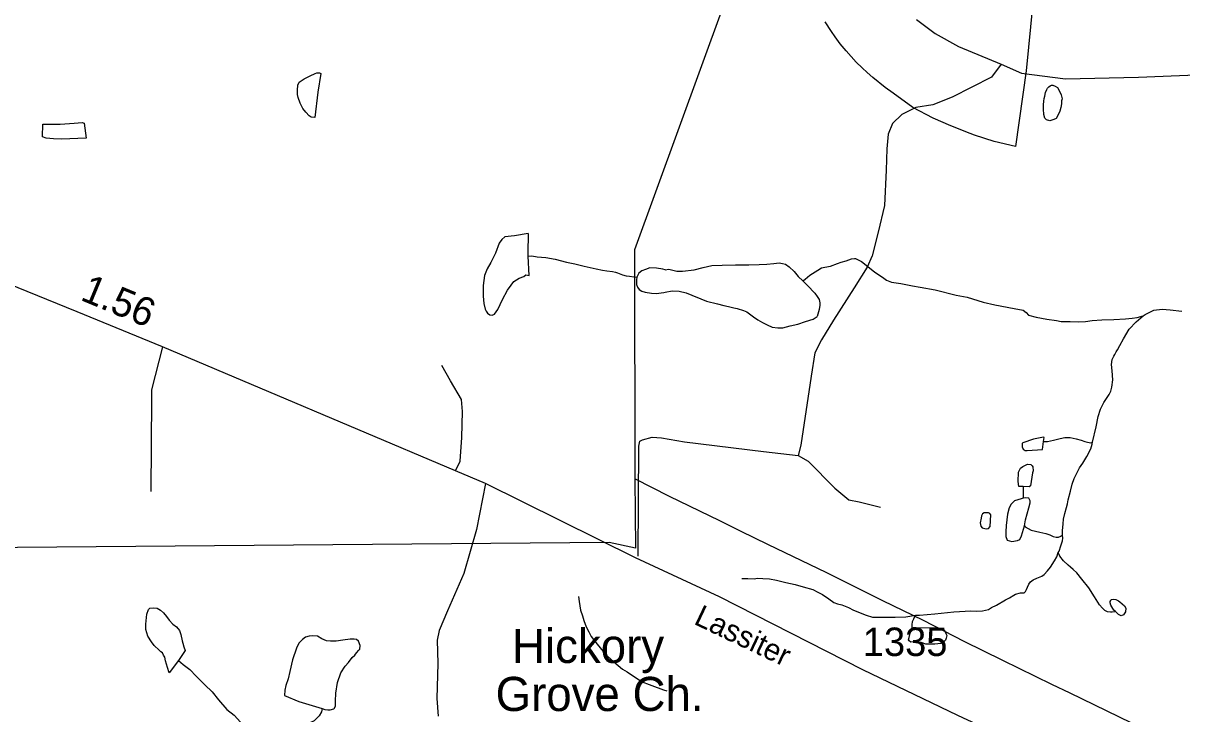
# Model space of a CAD drawing. Extents: x 2082433 to 2279600, y 546599 to 755198.
# Drawn here: x 2146074 to 2151168, y 635593 to 638629 of the extents above; entities that cross this region are included whole.
import ezdxf

# ---------------------------------------------------------------- set-up
doc = ezdxf.new("R2010")
doc.units = 0
for name, color, linetype in [('Exist Boundary Political Fire Districts', 7, 'Continuous'), ('Exist Cultural Church Label', 7, 'Continuous'), ('Exist Hydrographic Misc Water Feature', 7, 'Continuous'), ('Exist Road Non-System Type 51', 7, 'Continuous'), ('Exist Road Secondary Mileage Hundredths English Label', 7, 'Continuous'), ('Exist Road Secondary Type 51 Attributed', 7, 'Continuous'), ('Exist Road Secondary Type 51 Label', 7, 'Continuous'), ('Exist Road Secondary Type 51 Number Label', 7, 'Continuous')]:
    doc.layers.add(name, color=color, linetype=linetype)

msp = doc.modelspace()

# ---------------------------------------------------------------- linework, layer by layer
at = {"layer": 'Exist Boundary Political Fire Districts'}
for points in [[(2149345.1, 639234.6), (2148761.9, 637632), (2148762.7, 636625.8)], [(2150513, 638716), (2150482.9, 638419.1), (2150437, 638086.3), (2150343.1, 638109), (2150255.7, 638136.9), (2150236.4, 638143.4), (2150151.5, 638177.4), (2150074.9, 638211.1), (2149985, 638257.7), (2149898.1, 638320.6), (2149863.4, 638346.3), (2149809.9, 638389.3), (2149783.7, 638412.2), (2149761.9, 638431.9), (2149736.5, 638457), (2149713.3, 638481.9), (2149691.4, 638506.9), (2149665.2, 638538.5), (2149643.8, 638568), (2149627.4, 638591.5), (2149599.5, 638635.2)], [(2148762.7, 636625.8), (2148766, 636321.8), (2148650.1, 636346.6), (2144312.3, 636309), (2140471.4, 635994.8)], [(2152256, 634907.7), (2152199.6, 634933.1), (2152108.6, 634977), (2152016.1, 635021.2), (2151940.2, 635057.1), (2151321.2, 635370.7), (2150676.1, 635684), (2150596.7, 635722.7), (2150381.2, 635828.1), (2150211.2, 635910.6), (2150032.4, 636002.9), (2149852.8, 636090.6), (2149603.8, 636215), (2149351, 636336.1), (2149227.6, 636396.8), (2149135.9, 636441.9), (2148915.7, 636549.1), (2148762.7, 636625.8)]]:
    msp.add_lwpolyline(points, dxfattribs=at)
at = {"layer": 'Exist Hydrographic Misc Water Feature'}
msp.add_line((2150998.2, 637341.8), (2151006, 637347.9), dxfattribs=at)
for points in [[(2147369, 638325.8), (2147355.4, 638213.8), (2147339.7, 638215.8), (2147331.3, 638222), (2147315.7, 638237.7), (2147303.4, 638253.8), (2147291.7, 638277.5), (2147282.9, 638301.5), (2147279.4, 638315.4), (2147279.4, 638333.6), (2147280.8, 638355.7), (2147287, 638369.4), (2147308.9, 638383.5), (2147334.7, 638397.9), (2147356.7, 638407.9), (2147364.7, 638410), (2147376.6, 638409.8), (2147382.7, 638408.1), (2147369, 638325.8)], [(2150562.7, 638297.5), (2150564.7, 638307.7), (2150568.8, 638323.7), (2150574.8, 638337.4), (2150576.8, 638343.6), (2150582.8, 638349.6), (2150588.7, 638353.5), (2150594.5, 638355.9), (2150600.4, 638355.8), (2150610.9, 638351.8), (2150620.9, 638345.8), (2150630.5, 638329.8), (2150636.9, 638313.8), (2150641, 638296.1), (2150638.9, 638288), (2150639.2, 638274.1), (2150635.3, 638258.1), (2150631.2, 638242.1), (2150621.5, 638220), (2150615.4, 638210), (2150605.3, 638205.8), (2150587.7, 638199.6), (2150573.3, 638203.7), (2150565.3, 638211.5), (2150561.2, 638227.5), (2150559.2, 638251.3), (2150559.4, 638269.6), (2150560.6, 638285.6), (2150562.7, 638297.5)], [(2146242.6, 638119), (2146206.3, 638120.8), (2146174.3, 638122.8), (2146158.4, 638128.9), (2146160, 638184.6), (2146190.3, 638184.9), (2146236.1, 638184.8), (2146297.6, 638189.3), (2146333.7, 638191.5), (2146341.9, 638189.5), (2146350.5, 638123.3), (2146242.6, 638119)], [(2148294, 637604.3), (2148294, 637622.2), (2148295.4, 637700.2), (2148293.2, 637704.2), (2148233.7, 637693.7), (2148191.7, 637689.5), (2148177.9, 637677.8), (2148165.8, 637661.4), (2148150, 637617.6), (2148130.1, 637577.6), (2148113.9, 637549.6), (2148102.5, 637519.3), (2148096.5, 637475.6), (2148096.5, 637429.4), (2148098.8, 637397.4), (2148104.7, 637371.3), (2148109.2, 637363.3), (2148115.4, 637353.5), (2148125.4, 637347.6), (2148135.3, 637345.7), (2148145.3, 637349.8), (2148160.9, 637369.7), (2148181, 637413.7), (2148202.9, 637455.9), (2148218.5, 637477.8), (2148230.4, 637493.9), (2148254.6, 637508.1), (2148274.1, 637516.1), (2148284.1, 637522.3), (2148298.3, 637520.1), (2148294, 637604.3)], [(2148294, 637604.3), (2148310, 637606.3), (2148334, 637602.3), (2148372.1, 637598.6), (2148412.1, 637590.9), (2148461.9, 637578.9), (2148499.6, 637571.2), (2148539.6, 637561.5), (2148592.1, 637549.5), (2148620, 637543.6), (2148640.3, 637539.8), (2148664.1, 637537.8), (2148678.4, 637534), (2148686, 637532), (2148708.4, 637522.2), (2148724.2, 637518.2), (2148740, 637516.2), (2148758.4, 637514.2), (2148772.2, 637512.5)], [(2148895.8, 637545), (2148911.8, 637547), (2148947.9, 637539.1), (2148971.7, 637538.8), (2149023.8, 637545.1), (2149063.5, 637555.3), (2149101.5, 637563.3), (2149147.4, 637565.7), (2149205.2, 637566.3), (2149263.5, 637566.4), (2149309.4, 637568.8), (2149343.4, 637568.9), (2149373.4, 637572.9), (2149397.2, 637575.4), (2149411.3, 637573.2), (2149425.7, 637569.5), (2149441.4, 637557.3), (2149463.6, 637537.3), (2149481.6, 637515.5), (2149502.1, 637495.8)], [(2149502.1, 637495.8), (2149511.6, 637503.7), (2149531.5, 637521.8), (2149567.6, 637543.9), (2149583.3, 637554.1), (2149597.7, 637556.4), (2149623.5, 637560.7), (2149653.5, 637572.7), (2149669.5, 637578.8), (2149691.2, 637584.8), (2149715.2, 637593), (2149729.1, 637594.9), (2149733.2, 637595.1), (2149759.1, 637581.1), (2149779.4, 637565.4), (2149817.5, 637533.7), (2149851.5, 637511.9), (2149869.6, 637499.9), (2149891.7, 637490), (2149931.7, 637484.4), (2149983.6, 637474.5), (2150017.8, 637468.5), (2150083.9, 637456.9), (2150176.1, 637433.7), (2150223.7, 637424), (2150294.1, 637402.4), (2150345.3, 637390.6), (2150430.6, 637374.1), (2150470.6, 637366.8), (2150482.9, 637356.8), (2150494.2, 637345)], [(2148895.8, 637545), (2148885.8, 637546.9), (2148857.9, 637552.7), (2148828.1, 637552.8), (2148809.7, 637546.6), (2148793.9, 637540.5), (2148780.2, 637530.4), (2148772.2, 637512.5)], [(2148772.2, 637512.5), (2148770.1, 637500.3), (2148770.1, 637480.4), (2148774.6, 637468.4), (2148782.2, 637458.3), (2148794.1, 637450.4), (2148808.2, 637446.6), (2148836.1, 637442.8), (2148858.3, 637440.7), (2148878.4, 637443), (2148890.5, 637444.7), (2148896.4, 637447.1)], [(2149502.1, 637495.8), (2149521.8, 637475.8), (2149554.4, 637442.1), (2149563.9, 637428.1), (2149573.9, 637414.4), (2149576.4, 637400.2), (2149576.4, 637390.1), (2149572.5, 637370), (2149564.5, 637340)], [(2148896.4, 637447.1), (2148926.4, 637453.1), (2148958.1, 637450.7), (2148988.3, 637443), (2149012.7, 637433.2), (2149052.5, 637417.4), (2149078.5, 637407.4), (2149126.3, 637395.7), (2149154.8, 637387.7), (2149174.5, 637383.9), (2149198.7, 637378.3), (2149212.8, 637374.1), (2149240.9, 637366.2), (2149254.6, 637360.5), (2149285.2, 637338.8)], [(2151006, 637347.9), (2151045.2, 637367.1), (2151080.8, 637371.1), (2151116.1, 637369), (2151167.8, 637363.2)], [(2149285.2, 637338.8), (2149304.1, 637325.4), (2149324.6, 637312.6), (2149345.1, 637302.6), (2149366.6, 637292.4), (2149390.8, 637289.2), (2149413.4, 637289.8), (2149445.5, 637298.7), (2149479.4, 637306.2), (2149512.8, 637317.8), (2149547.3, 637328), (2149564.5, 637340)], [(2150494.2, 637345), (2150528, 637337), (2150573.9, 637327.3), (2150616, 637321.7), (2150637.9, 637318), (2150676.3, 637317.9), (2150714.2, 637316.2), (2150744.1, 637318.1), (2150773.9, 637322.6), (2150815.9, 637324.7), (2150868.2, 637327), (2150919.9, 637329.3), (2150950, 637331.6), (2150972, 637335.6), (2150998.2, 637341.8)], [(2150775.1, 636786.6), (2150790.7, 636854.9), (2150800.5, 636900.8), (2150810.6, 636933), (2150824.1, 636960.9), (2150848.1, 636997.1), (2150855.9, 637011.3), (2150860.2, 637028.9), (2150863.9, 637061.2), (2150861.4, 637100.9), (2150859, 637129.2), (2150861.4, 637151.2), (2150865.3, 637159.1), (2150868.8, 637165.1), (2150873.1, 637172.9), (2150878.9, 637185), (2150885, 637193), (2150894.9, 637211.4), (2150910.8, 637241.4), (2150936.5, 637283.4), (2150966.2, 637315.8), (2150998.2, 637341.8)], [(2150559.4, 636789.7), (2150563.1, 636807.3), (2150559.2, 636809.5), (2150514.9, 636801.2), (2150469.2, 636785), (2150465.7, 636781.1), (2150465.5, 636766.9), (2150469.4, 636757.1), (2150479.4, 636751.1), (2150487.4, 636751.1), (2150555.3, 636755.4), (2150559.4, 636789.7)], [(2150559.4, 636789.7), (2150577.2, 636789.8), (2150603.3, 636795.6), (2150633, 636804.1), (2150653.3, 636807.9), (2150677.1, 636808.4), (2150702.9, 636802.4), (2150724.9, 636796.3), (2150740.9, 636790.6), (2150753, 636786.7), (2150767.1, 636784.6), (2150775.1, 636786.6)], [(2150643.7, 636380.3), (2150643.7, 636398.1), (2150645.3, 636427.9), (2150647.4, 636448.2), (2150652.9, 636474.2), (2150661.1, 636500.1), (2150664.6, 636516.2), (2150668.5, 636534.3), (2150678.1, 636572.1), (2150686.1, 636602.2), (2150693.9, 636628.2), (2150703.9, 636648.1), (2150717.7, 636674.5), (2150731.8, 636694.7), (2150749.5, 636724.8), (2150767.5, 636758.6), (2150773.5, 636778.8), (2150775.1, 636786.6)], [(2150470.4, 636593), (2150450.5, 636592.8), (2150448.2, 636615.1), (2150449.7, 636655), (2150457.9, 636672.8), (2150468.1, 636681), (2150489.7, 636691.1), (2150503.8, 636689.3), (2150510.2, 636683.1), (2150512, 636679.2), (2150513.7, 636661.5), (2150511.8, 636653.2), (2150502.2, 636595.1), (2150496.4, 636591.1), (2150470.4, 636593)], [(2150470.4, 636593), (2150470.4, 636567.1), (2150470.8, 636549.2), (2150470.6, 636541.1)], [(2150470.6, 636541.1), (2150460.6, 636538.9), (2150432.5, 636529), (2150417.1, 636514.7), (2150408.9, 636498.9), (2150401.3, 636470.9), (2150395.3, 636420.7), (2150393.7, 636392.5), (2150393.7, 636372.6), (2150399.7, 636356.7), (2150420, 636350.8), (2150445.6, 636355), (2150455.6, 636359.2), (2150463.4, 636375.1), (2150471.4, 636405.1), (2150475.5, 636419.1)], [(2150475.5, 636419.1), (2150481.1, 636445.4), (2150495.2, 636499.3), (2150500.5, 636521.1), (2150500.5, 636529.2), (2150494.6, 636541.1), (2150482.5, 636543.3), (2150470.6, 636541.1)], [(2150281.3, 636432.2), (2150283.6, 636418.1), (2150289.5, 636410.3), (2150307.6, 636406.4), (2150317.2, 636408.2), (2150325.4, 636416.3), (2150327.3, 636468.3), (2150323.2, 636474.2), (2150317, 636476.3), (2150299.2, 636476.1), (2150291.4, 636472.1), (2150287.1, 636464.2), (2150285.2, 636453.9), (2150281.3, 636432.2)], [(2150475.5, 636419.1), (2150479.4, 636415.2), (2150505.7, 636401.1), (2150543.6, 636391.3), (2150569.4, 636385.8), (2150587.5, 636379.9), (2150601.4, 636372.1), (2150615.6, 636369.9), (2150625.8, 636370), (2150635.9, 636374.2), (2150643.7, 636380.3)], [(2150623.8, 636302.1), (2150627.9, 636308), (2150635.7, 636332), (2150643.7, 636354.3), (2150643.9, 636366.1), (2150643.7, 636380.3)], [(2149997.3, 636026.6), (2150013.9, 636026.6), (2150081.6, 636032.9), (2150165.7, 636041.7), (2150215.3, 636043.9), (2150237.3, 636045.9), (2150265.5, 636044), (2150291.4, 636046.2), (2150317.4, 636052.4), (2150331.6, 636060.4), (2150353.1, 636070.5), (2150392.9, 636094.9), (2150409.3, 636103), (2150429, 636115), (2150437, 636119.1), (2150458.7, 636125.1), (2150474.9, 636125.1), (2150481.1, 636131.1), (2150485, 636139.4), (2150488.9, 636149.4), (2150494.6, 636163.5), (2150502.6, 636173.3), (2150514.5, 636181.6), (2150530.7, 636189.7), (2150552.4, 636197.8), (2150562.3, 636205.6), (2150576.4, 636221.7), (2150590.1, 636237.9), (2150608, 636266), (2150618.2, 636283.9), (2150623.8, 636302.1)], [(2150875.4, 636043.5), (2150871.7, 636041.6), (2150861.4, 636039.5), (2150853.4, 636039.5), (2150841.3, 636041.3), (2150829.6, 636047.2), (2150819.4, 636057.2), (2150805.5, 636073.1), (2150783.1, 636106.9), (2150758.7, 636146.7), (2150728.4, 636184.5), (2150706.2, 636212.6), (2150690.6, 636228.4), (2150678.3, 636238.4), (2150668.1, 636246.4), (2150648, 636266.1), (2150631.8, 636285.9), (2150623.8, 636302.1)], [(2149233.3, 636188.4), (2149237, 636188.2), (2149259.2, 636188.5), (2149287, 636186.8), (2149302.6, 636188.9), (2149325.2, 636188.7), (2149355.1, 636187), (2149385.1, 636181.2), (2149427.3, 636171.2), (2149467.3, 636161.5), (2149503.2, 636152), (2149545.2, 636140), (2149567.1, 636128.2), (2149587.6, 636118.2), (2149615.3, 636098.6), (2149637.3, 636082.7), (2149653.3, 636076.6), (2149673.6, 636072.7), (2149701.7, 636060.7), (2149723.6, 636049), (2149779.4, 636027.5), (2149807.9, 636017.5), (2149844.2, 636017.7), (2149873.9, 636017.7), (2149907.5, 636018.3), (2149953.9, 636020.2), (2149997.3, 636026.6)], [(2148515.8, 636109.5), (2148518.1, 636087.2), (2148520.4, 636067.5), (2148524.5, 636049.4), (2148532.7, 636023.4), (2148538.6, 636003.4), (2148548.9, 635975.5), (2148560.3, 635953.5), (2148570.8, 635933.7), (2148597, 635899.7), (2148623.1, 635867.8), (2148643.2, 635846.1), (2148671.1, 635822), (2148709.2, 635790.3), (2148729.3, 635778.3), (2148761.3, 635756.4), (2148795.5, 635734.7), (2148825.5, 635722.8), (2148849.9, 635713.1), (2148877.6, 635703.2), (2148889.4, 635698.9), (2148903.8, 635695.1)], [(2150875.4, 636043.5), (2150869, 636049.3), (2150854.9, 636071.3), (2150853.2, 636081.3), (2150853.2, 636087.4), (2150855.3, 636091.6), (2150856.7, 636095.4), (2150867, 636097.5), (2150876.8, 636095.6), (2150888.9, 636089.7), (2150895.1, 636085.5), (2150915.2, 636067.9), (2150921.1, 636057.7), (2150919.7, 636041.7), (2150911.5, 636027.9), (2150901.4, 636023.7), (2150889.1, 636029.6), (2150875.4, 636043.5)], [(2146756.1, 635827.7), (2146715.9, 635773.7), (2146708.1, 635797.7), (2146699.9, 635825.7), (2146695.8, 635841.7), (2146689.9, 635851.5), (2146685.5, 635861.5), (2146679.4, 635865.6), (2146671.8, 635873.3), (2146649.7, 635893.3), (2146637.4, 635909.3), (2146621.4, 635935.3), (2146613.2, 635963.3), (2146613, 635987.2), (2146615.4, 636017.3), (2146616.9, 636031.3), (2146624.8, 636051.2), (2146630.6, 636057.2), (2146646.6, 636059.2), (2146663, 636057.2), (2146676.9, 636049.4), (2146691.1, 636037.5), (2146703.2, 636021.4), (2146715.1, 636005.5), (2146731.3, 635987.6), (2146747.1, 635975.9), (2146761.4, 635959.9), (2146767.4, 635942), (2146773.3, 635913.9), (2146775.6, 635903.9), (2146779.7, 635887.8), (2146785.4, 635871.9), (2146756.1, 635827.7)], [(2149982.2, 635966.4), (2149981.8, 635984.4), (2149983.8, 635998.7), (2149990, 636010.7), (2149997.3, 636026.6)], [(2149982.2, 635966.4), (2149985.9, 635972.4), (2149999.8, 635972.7), (2150096, 635971.1), (2150118.1, 635965.3), (2150126.1, 635957.2), (2150132.3, 635943.4), (2150134.3, 635937.4), (2150132.3, 635925.5), (2150128.4, 635917.6), (2150124.3, 635913.3), (2150108.5, 635903.1), (2150082.4, 635899), (2150042.5, 635899), (2150022.4, 635906.8), (2149994.7, 635910.6), (2149976.4, 635908.5), (2149968.4, 635914.6), (2149966.6, 635918.5), (2149968.2, 635928.4), (2149974.4, 635954.6), (2149982.2, 635966.4)], [(2147388.5, 635616.4), (2147400.6, 635612.6), (2147412.7, 635610.8), (2147422.9, 635610.9), (2147438.9, 635615), (2147442.6, 635618.9), (2147446.3, 635628.9), (2147446.3, 635648.7), (2147447.9, 635684.9), (2147456.1, 635730.8), (2147469.9, 635772.9), (2147489.8, 635803.1), (2147503.9, 635819.2), (2147519.9, 635841.2), (2147531.4, 635851.2), (2147539.4, 635861.3), (2147549.4, 635873.2), (2147553.1, 635877.5), (2147555.4, 635893.4), (2147547.2, 635913.3), (2147539.4, 635919.4), (2147528.9, 635921.3), (2147511.1, 635921.2), (2147479.1, 635917.1), (2147449, 635912.7), (2147425.2, 635912.7), (2147407.1, 635914.6), (2147386.8, 635922.5), (2147367.1, 635934.4), (2147347, 635936.2), (2147331, 635934.2), (2147315.1, 635930.1), (2147301.3, 635920), (2147287.2, 635906), (2147279.4, 635892.1), (2147275.1, 635882.2), (2147257.4, 635830.2), (2147245.7, 635780), (2147238.4, 635747.9), (2147228.1, 635717.8), (2147224.4, 635698.1), (2147222.6, 635674), (2147286.3, 635648.2), (2147388.5, 635616.4)], [(2146756.1, 635827.7), (2146777.6, 635809.8), (2146805.9, 635788.1), (2146834.2, 635758.3), (2146872.6, 635720.5), (2146904.3, 635690.5), (2146932.4, 635654.6), (2146968.3, 635612.7), (2147001.1, 635587.1), (2147028.8, 635556.9), (2147055.3, 635529), (2147083.1, 635495.2), (2147107.3, 635469.6), (2147123.3, 635445.7), (2147141.4, 635415.8), (2147147.5, 635401.5)], [(2147388.5, 635616.4), (2147384.6, 635602.5), (2147374.3, 635584.6), (2147364.7, 635574.7), (2147352.8, 635562.7), (2147314.8, 635544.5), (2147289, 635534.2), (2147263, 635523.9), (2147247.4, 635516.2), (2147239.4, 635512.1), (2147225.2, 635496), (2147213.1, 635479.9), (2147201.3, 635470), (2147185.3, 635457.8), (2147175.4, 635449.6), (2147167.4, 635437.8), (2147159.2, 635421.6), (2147151.8, 635409.8), (2147147.5, 635401.5)]]:
    msp.add_lwpolyline(points, dxfattribs=at)
at = {"layer": 'Exist Road Non-System Type 51'}
for points in [[(2150374, 638448.8), (2150331.3, 638391.9), (2150157.8, 638303.7), (2150072.5, 638269.6), (2149998.6, 638258.2), (2149936, 638226.9), (2149896.2, 638187.1), (2149876.3, 638141.6), (2149870.6, 638076.2), (2149867.7, 637982.3), (2149860.6, 637827.3), (2149832.2, 637710.7), (2149806.6, 637605.5), (2149783.8, 637557.1), (2149726.9, 637466.1), (2149635.9, 637323.9), (2149583.3, 637237.2), (2149554.9, 637180.3), (2149537.8, 637077.9), (2149492.3, 636773.6), (2149480.9, 636728.1)], [(2146686, 637206.3), (2146638.2, 637016.8), (2146638.2, 636979.8), (2146635.4, 636570.2)], [(2147974.8, 636661.2), (2147994.5, 636703.4), (2148002.9, 636807.3), (2148005.7, 636922.5), (2148000.6, 636974.1), (2147952.3, 637057.4), (2147914.4, 637124.8)], [(2148777, 636285.8), (2148779.9, 636769.3), (2148785.5, 636792.1), (2148796.9, 636797.8), (2148839.6, 636809.1), (2148879.4, 636806.3), (2148981.8, 636789.2), (2149328.8, 636746.6), (2149480.9, 636728.1)], [(2149480.9, 636728.1), (2149525, 636703.9), (2149641.6, 636584.5), (2149704.2, 636533.3), (2149749.7, 636524.7), (2149843.5, 636502)], [(2148106.9, 636605.1), (2148067.4, 636403.9), (2148010.5, 636210.5), (2147939.4, 636045.5), (2147902.5, 635960.2), (2147893.9, 635917.5), (2147896.8, 635815.1), (2147892.5, 635660.1), (2147898.2, 635583.3)]]:
    msp.add_lwpolyline(points, dxfattribs=at)
at = {"layer": 'Exist Road Secondary Type 51 Attributed'}
for points in [[(2150001.4, 638645), (2150082.9, 638583.3), (2150186.3, 638526), (2150374, 638448.8), (2150463.5, 638409.3), (2150656.3, 638383.9), (2150976.9, 638391.9), (2151446.3, 638410)], [(2150506.8, 635423.7), (2150393.9, 635487.6), (2150182.3, 635586.7), (2149765.1, 635786.1), (2149134.9, 636107.7), (2148765.7, 636279.2), (2148106.9, 636605.1), (2147974.8, 636661.2), (2146686, 637206.3), (2146310.3, 637359.4), (2146004.1, 637484.4), (2145813, 637568.7), (2145539.1, 637686.7), (2145436.6, 637742.9), (2145350.9, 637786.4), (2145289.8, 637831.3), (2145177.4, 637922.7), (2145053.8, 638046.3), (2144744.8, 638394.6), (2144605.7, 638518.2), (2144452.6, 638632)]]:
    msp.add_lwpolyline(points, dxfattribs=at)

# ---------------------------------------------------------------- texts
at = {"layer": 'Exist Cultural Church Label'}
for s, p in [('Hickory ', (2148222.8, 635816.8)), ('Grove Ch.', (2148150.7, 635605.7))]:
    msp.add_text(s, height=150, dxfattribs=at).set_placement(p)
at = {"layer": 'Exist Road Secondary Mileage Hundredths English Label'}
msp.add_text('1.56', height=125, rotation=337.5146, dxfattribs=at).set_placement((2146320.3, 637413.8))
at = {"layer": 'Exist Road Secondary Type 51 Label'}
msp.add_text('Lassiter', height=95, rotation=334.5841, dxfattribs=at).set_placement((2149017.8, 635990))
at = {"layer": 'Exist Road Secondary Type 51 Number Label'}
msp.add_text('1335', height=125, dxfattribs=at).set_placement((2149765.2, 635847.5))

doc.saveas('drawing.dxf')
